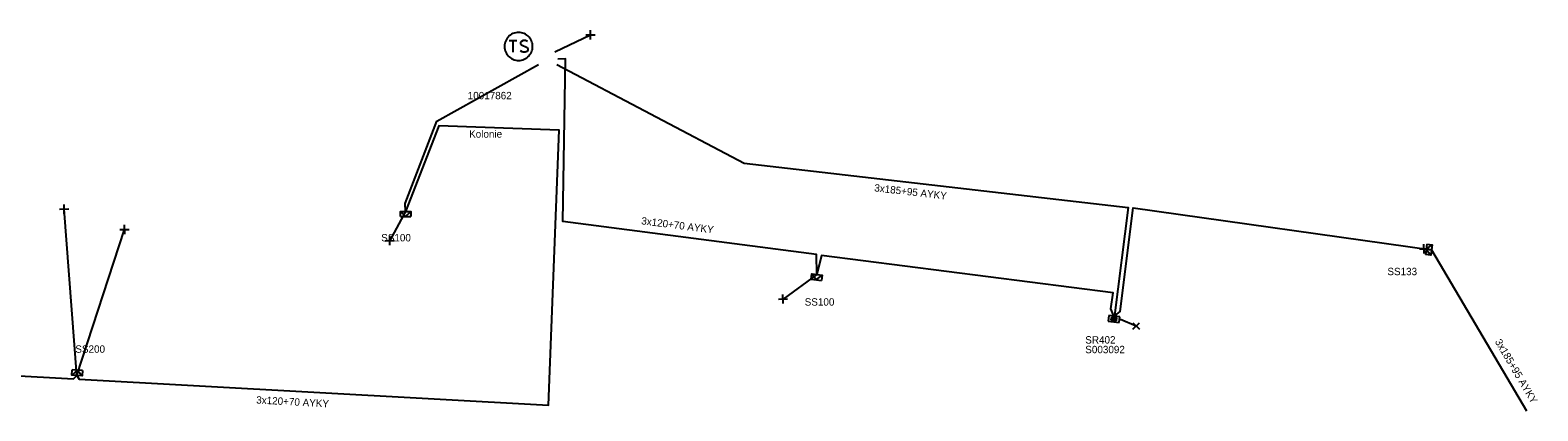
# Model space of a CAD drawing. Extents: x -762894 to -762498, y -1152897 to -1152214.
# Drawn here: x -762701.3 to -762498.5, y -1152897.1 to -1152845.8 of the extents above; entities that cross this region are included whole.
import ezdxf

# ---------------------------------------------------------------- set-up
doc = ezdxf.new("R2010")
doc.units = 0
for name, color, linetype in [('Vrstva 25', 7, 'Continuous'), ('Vrstva 26', 7, 'Continuous'), ('Vrstva 27', 7, 'Continuous'), ('Vrstva 28', 7, 'Continuous'), ('Vrstva 29', 7, 'Continuous'), ('Vrstva 30', 7, 'Continuous'), ('Vrstva 31', 7, 'Continuous'), ('Vrstva 33', 7, 'Continuous'), ('Vrstva 34', 7, 'Continuous'), ('Vrstva 5', 7, 'Continuous'), ('Vrstva 59', 7, 'Continuous'), ('Vrstva 6', 7, 'Continuous')]:
    doc.layers.add(name, color=color, linetype=linetype)

msp = doc.modelspace()

# ---------------------------------------------------------------- linework, layer by layer
at = {"layer": 'Vrstva 25'}
for points in [[(-762633.677, -1152847.971), (-762633.688, -1152847.774), (-762633.719, -1152847.578), (-762633.77, -1152847.387), (-762633.842, -1152847.202), (-762633.931, -1152847.027), (-762634.039, -1152846.861), (-762634.163, -1152846.707), (-762634.303, -1152846.567), (-762634.457, -1152846.443), (-762634.623, -1152846.335), (-762634.799, -1152846.245), (-762634.983, -1152846.174), (-762635.37, -1152846.092), (-762635.37, -1152846.092), (-762635.567, -1152846.081), (-762635.765, -1152846.092), (-762635.961, -1152846.123), (-762636.151, -1152846.174), (-762636.337, -1152846.245), (-762636.512, -1152846.335), (-762636.678, -1152846.443), (-762636.832, -1152846.567), (-762636.972, -1152846.707), (-762637.096, -1152846.861), (-762637.204, -1152847.027), (-762637.294, -1152847.202), (-762637.365, -1152847.387), (-762637.416, -1152847.578), (-762637.447, -1152847.774), (-762637.458, -1152847.971), (-762637.447, -1152848.169), (-762637.416, -1152848.365), (-762637.365, -1152848.555), (-762637.294, -1152848.74), (-762637.204, -1152848.916), (-762637.096, -1152849.082), (-762636.971, -1152849.236), (-762636.832, -1152849.375), (-762636.678, -1152849.5), (-762636.512, -1152849.608), (-762636.336, -1152849.698), (-762636.151, -1152849.769), (-762635.961, -1152849.82), (-762635.765, -1152849.851), (-762635.567, -1152849.862), (-762635.37, -1152849.851), (-762635.175, -1152849.82), (-762634.983, -1152849.769), (-762634.799, -1152849.698), (-762634.623, -1152849.608), (-762634.457, -1152849.5), (-762634.303, -1152849.375), (-762634.163, -1152849.236), (-762634.039, -1152849.082), (-762633.931, -1152848.916), (-762633.842, -1152848.74), (-762633.77, -1152848.555), (-762633.719, -1152848.365), (-762633.688, -1152848.169), (-762633.677, -1152847.971)], [(-762636.829, -1152847.188), (-762635.821, -1152847.188)], [(-762636.325, -1152847.188), (-762636.325, -1152848.762)], [(-762634.372, -1152847.314), (-762634.624, -1152847.188), (-762634.939, -1152847.188), (-762635.191, -1152847.314), (-762635.317, -1152847.502), (-762635.317, -1152847.566), (-762635.191, -1152847.754), (-762634.435, -1152848.132), (-762634.309, -1152848.29), (-762634.309, -1152848.448), (-762634.435, -1152848.636), (-762634.687, -1152848.762), (-762634.939, -1152848.762), (-762635.065, -1152848.7), (-762635.317, -1152848.574)]]:
    msp.add_lwpolyline(points, dxfattribs=at)
at = {"layer": 'Vrstva 28'}
for points in [[(-762556.182, -1152884.235), (-762556.273, -1152884.98)], [(-762556.273, -1152884.98), (-762554.784, -1152885.162)], [(-762554.693, -1152884.418), (-762556.182, -1152884.235)], [(-762555.835, -1152884.462), (-762555.881, -1152884.837)], [(-762555.881, -1152884.837), (-762555.142, -1152884.928)], [(-762555.096, -1152884.553), (-762555.835, -1152884.462)], [(-762555.794, -1152884.515), (-762555.828, -1152884.796)], [(-762555.828, -1152884.796), (-762555.183, -1152884.875)], [(-762555.149, -1152884.594), (-762555.794, -1152884.515)], [(-762555.753, -1152884.568), (-762555.776, -1152884.755)], [(-762555.776, -1152884.755), (-762555.225, -1152884.823)], [(-762555.202, -1152884.635), (-762555.753, -1152884.568)], [(-762555.712, -1152884.62), (-762555.723, -1152884.714)], [(-762555.723, -1152884.714), (-762555.266, -1152884.77)], [(-762555.254, -1152884.676), (-762555.712, -1152884.62)], [(-762555.676, -1152884.672), (-762555.301, -1152884.718)], [(-762555.266, -1152884.77), (-762555.254, -1152884.676)], [(-762555.225, -1152884.823), (-762555.202, -1152884.635)], [(-762555.183, -1152884.875), (-762555.149, -1152884.594)], [(-762555.142, -1152884.928), (-762555.096, -1152884.553)], [(-762554.784, -1152885.162), (-762554.693, -1152884.418)]]:
    msp.add_lwpolyline(points, dxfattribs=at)
at = {"layer": 'Vrstva 31'}
for points in [[(-762650.773, -1152870.9), (-762651.473, -1152870.2)], [(-762651.473, -1152870.9), (-762651.473, -1152870.2), (-762650.073, -1152870.2), (-762650.073, -1152870.9)], [(-762651.473, -1152870.9), (-762650.073, -1152870.9)], [(-762650.773, -1152870.9), (-762650.073, -1152870.2)], [(-762513.389, -1152874.607), (-762513.56, -1152875.997)], [(-762513.389, -1152874.607), (-762512.694, -1152874.693), (-762512.865, -1152876.082), (-762513.56, -1152875.997)], [(-762513.474, -1152875.302), (-762512.694, -1152874.693)], [(-762513.474, -1152875.302), (-762512.865, -1152876.082)], [(-762596.223, -1152879.319), (-762596.138, -1152878.624), (-762594.748, -1152878.795), (-762594.833, -1152879.49)], [(-762596.223, -1152879.319), (-762594.833, -1152879.49)], [(-762595.528, -1152879.404), (-762596.138, -1152878.624)], [(-762595.528, -1152879.404), (-762594.748, -1152878.795)], [(-762694.22, -1152891.641), (-762694.269, -1152892.339), (-762695.665, -1152892.241), (-762695.617, -1152891.543)], [(-762694.918, -1152891.592), (-762695.665, -1152892.241)], [(-762694.22, -1152891.641), (-762695.617, -1152891.543)], [(-762694.918, -1152891.592), (-762694.269, -1152892.339)]]:
    msp.add_lwpolyline(points, dxfattribs=at)
at = {"layer": 'Vrstva 34'}
for points in [[(-762626.525, -1152846.411), (-762625.275, -1152846.389)], [(-762625.889, -1152847.025), (-762625.911, -1152845.775)], [(-762696.679, -1152870.505), (-762696.701, -1152869.255)], [(-762697.315, -1152869.891), (-762696.065, -1152869.869)], [(-762689.185, -1152872.641), (-762687.935, -1152872.619)], [(-762688.549, -1152873.255), (-762688.571, -1152872.005)], [(-762652.869, -1152874.755), (-762652.891, -1152873.505)], [(-762653.505, -1152874.141), (-762652.255, -1152874.119)], [(-762514.395, -1152875.261), (-762513.145, -1152875.239)], [(-762513.759, -1152875.875), (-762513.781, -1152874.625)], [(-762599.989, -1152882.625), (-762600.011, -1152881.375)], [(-762600.625, -1152882.011), (-762599.375, -1152881.989)], [(-762552.942, -1152885.188), (-762552.058, -1152886.072)], [(-762552.942, -1152886.072), (-762552.058, -1152885.188)]]:
    msp.add_lwpolyline(points, dxfattribs=at)
at = {"layer": 'Vrstva 5'}
for points in [[(-762743.72, -1152885.33), (-762743.69, -1152886.39), (-762740.9, -1152890.25), (-762695.44, -1152892.73), (-762694.97, -1152892.29), (-762694.69, -1152892.8), (-762631.53, -1152896.28), (-762630.13, -1152859.24), (-762646.31, -1152858.66), (-762650.77, -1152870.2), (-762650.83, -1152869.13), (-762646.58, -1152858.04), (-762632.87, -1152850.42)], [(-762630.44, -1152850.39), (-762605.22, -1152863.72), (-762553.55, -1152869.66), (-762555.43, -1152884.2)], [(-762555.55, -1152884.18), (-762555.9, -1152883.32), (-762555.59, -1152881.15), (-762594.8, -1152876.14), (-762595.44, -1152878.71), (-762595.49, -1152876), (-762629.62, -1152871.57), (-762629.27, -1152849.66), (-762630.28, -1152849.7)], [(-762555.3, -1152884.22), (-762554.65, -1152883.66), (-762552.88, -1152869.71), (-762512.78, -1152875.39), (-762500, -1152897.07)]]:
    msp.add_lwpolyline(points, dxfattribs=at)
at = {"layer": 'Vrstva 59'}
for points in [[(-762630.7, -1152848.7), (-762625.9, -1152846.4)], [(-762694.97, -1152892.29), (-762696.69, -1152869.88)], [(-762650.77, -1152870.2), (-762652.88, -1152874.13)], [(-762694.97, -1152892.29), (-762688.56, -1152872.63)], [(-762512.78, -1152875.39), (-762513.77, -1152875.25)], [(-762595.44, -1152878.71), (-762600, -1152882)], [(-762554.6, -1152884.7), (-762552.5, -1152885.63)]]:
    msp.add_lwpolyline(points, dxfattribs=at)

# ---------------------------------------------------------------- texts
at = {"layer": 'Vrstva 26'}
msp.add_text('10017862', height=0.9943, dxfattribs=at).set_placement((-762642.41, -1152855.09))
at = {"layer": 'Vrstva 27'}
msp.add_text('Kolonie', height=0.9943, dxfattribs=at).set_placement((-762642.22, -1152860.26))
at = {"layer": 'Vrstva 29'}
msp.add_text('S003092', height=0.9943, dxfattribs=at).set_placement((-762559.34, -1152889.3))
at = {"layer": 'Vrstva 30'}
msp.add_text('SR402', height=0.9943, dxfattribs=at).set_placement((-762559.34, -1152888))
at = {"layer": 'Vrstva 33'}
for s, p in [('SS100', (-762654.05, -1152874.24)), ('SS133', (-762518.7, -1152878.79)), ('SS100', (-762597.08, -1152882.89)), ('SS200', (-762695.19, -1152889.24))]:
    msp.add_text(s, height=0.9943, dxfattribs=at).set_placement(p)
at = {"layer": 'Vrstva 6'}
for s, height, rotation, p in [('3x185+95 AYKY', 0.99429, 353.43744, (-762587.76, -1152867.49)), ('3x120+70 AYKY', 0.99428, 352.71613, (-762619.11, -1152871.93)), ('3x185+95 AYKY', 0.99429, 300.53165, (-762504.28, -1152887.75)), ('3x120+70 AYKY', 0.99429, 356.8439, (-762670.88, -1152896.07))]:
    msp.add_text(s, height=height, rotation=rotation, dxfattribs=at).set_placement(p)

doc.saveas('drawing.dxf')
